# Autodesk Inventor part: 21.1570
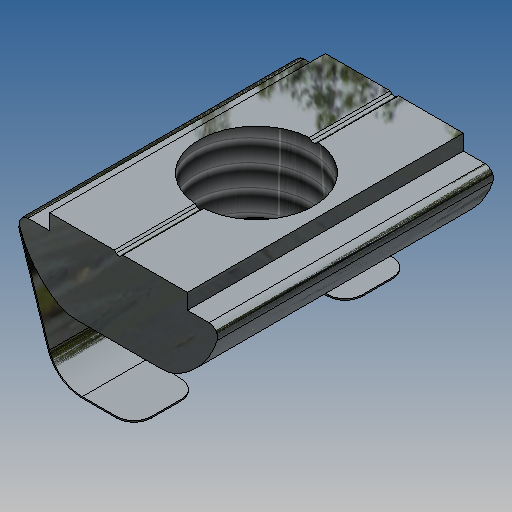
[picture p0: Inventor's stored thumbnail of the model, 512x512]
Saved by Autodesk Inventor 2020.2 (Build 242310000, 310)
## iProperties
Created: 2012-02
Part Number: 21.1570
Document SubType Name: Modeling
Designer: Administrator
Density: 7.85 g/cm^3
Material: Steel
Mass: 4.29634 g
Surface Area: 8.53534 cm^2
Volume: 0.547304 cm^3
Description: M8 SQUARE NUT 30
Vendor: S
Appearance: Zinc
Author: Administrator
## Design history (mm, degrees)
sketch "Sketch1"
  geometry: L1 (-4, 0)-(4, 0); L2 (4, 0)-(4, -0.9); L3 (-4, 0)-(-4, -0.9); L4 (-4, -0.9)-(-5.25, -0.9); L5 (4, -0.9)-(5.25, -0.9); L6 (-2.5, -4.6)-(2.5, -4.6); A1 r 5 centre (-0.966, -0.022) between (-5.726, -1.553) and (-3.522, -4.319); A2 r 5 centre (0.966, -0.022) between (3.522, -4.319) and (5.726, -1.553); A3 r 0.5 centre (5.25, -1.4) between (5.726, -1.553) and (5.25, -0.9); A4 r 0.5 centre (-5.25, -1.4) between (-5.25, -0.9) and (-5.726, -1.553); A5 r 2 centre (-2.5, -2.6) between (-3.522, -4.319) and (-2.5, -4.6); A6 r 2 centre (2.5, -2.6) between (2.5, -4.6) and (3.522, -4.319); 3 further points
  constraints: 12 end point, 12 point on circle, 8 tangent, 6 centre point, 2 equal length, 2 equal radius, 2 midpoint, 2 parallel, 2 perpendicular, 1 coincident, 1 collinear, 1 horizontal, 1 vertical alignment
  dimensions: "d0" = 0.9 distance of L1.end L2.end; "d1" = 8 distance of L1.start L1.end; "d2" = 4.6 distance between parallel lines of L6 L1; "d4" = 5 radius of A1; "d5" = 5 radius of A2 (= d4); "d6" = 0.5 radius of A3; "d7" = 2 radius of A5; "d8" = 11.5 dimension on A3 A4; "d9" = 5 distance of L6.start L6.end
extrude "Extrusion1" new body sketch "Sketch1" stored distance "d10" = 16; taper "d11" = 0 deg
sketch "Sketch2"
  geometry: L1 (-4, 0)-(4, 0) reference; L2 (-0.25, 0)-(0, -0.25); L3 (0, -0.25)-(0.25, 0); 2 further points
  constraints: 4 end point, 2 point on line, 1 midpoint, 1 vertical alignment
  dimensions: "d12" = 45 deg angle of L1 L2; "d13" = 90 deg angle of L3 L2; "d14" = 0.25 distance from line of L2.end L1
extrude "Extrusion2" cut sketch "Sketch2" extent not by distance; stored distance "d15" = 16; taper "d16" = 0 deg
fillet "Fillet1" dims "d17" = 0.2
sketch "Sketch3"
  geometry: 2 further points
  constraints: 1 coincident
hole "Hole1" sketch "Sketch3" at (4, 8) diameter "d18" = 6.647; stored, may be unused: countersink angle "d22" = 90 deg, drill point angle "d24" = 118 deg; dims "d19" = 6, "d20" = 4, "d21" = 2, "d23" = 8
sketch "Sketch4"
  geometry: L1 (-5.726, -1.553)-(-4.005, -6.901); L2 (-2.102, -8.288)-(0.898, -8.288); L3 (-4, 0)-(-0.25, 0) reference; L4 (0.898, -8.368)-(-2.102, -8.368); L5 (-4.082, -6.925)-(-5.802, -1.578); L6 (-5.802, -1.578)-(-5.726, -1.553); L7 (0.898, -8.288)-(0.898, -8.368); L8 (-4, -0.9)-(-5.25, -0.9) reference; A1 r 2 centre (-2.102, -6.288) between (-4.005, -6.901) and (-2.102, -8.288); A2 r 2.08 centre (-2.102, -6.288) between (-4.082, -6.925) and (-2.102, -8.368); A3 r 5 centre (-0.966, -0.022) between (-5.726, -1.553) and (-3.522, -4.319) reference; 1 further point
  constraints: 12 end point, 4 point on circle, 3 tangent, 2 centre point, 2 perpendicular, 1 horizontal, 2 other
  dimensions: "d26" = 2 radius of A1; "d27" = 0.08 distance between parallel lines of L5 L1; "d28" = 3 distance of L4.start L4.end; "d35" = 7.468 distance between parallel lines of L4 L8
extrude "Extrusion3" join sketch "Sketch4" stored distance "d29" = 16; taper "d30" = 0 deg
sketch "Sketch5"
  geometry: L1 (5, 0)-(5, -16) reference; L2 (2.5, -12.25)-(15.825, -12.25); L3 (15.825, -12.25)-(15.825, -3.75); L4 (15.825, -3.75)-(2.5, -3.75); C1 r 3.324 at (2.5, -8) reference; A1 r 4.25 centre (2.5, -8) between (2.5, -3.75) and (2.5, -12.25)
  constraints: 6 end point, 2 point on circle, 2 tangent, 1 centre point, 1 coincident, 1 perpendicular, 1 vertical, 1 vertical alignment
  dimensions: "d31" = 8.5 diameter of A1
extrude "Extrusion4" cut sketch "Sketch5" distance "d32" = 16; taper "d33" = 0 deg
fillet "Fillet2" dims "d34" = 1
body "Solid1"
